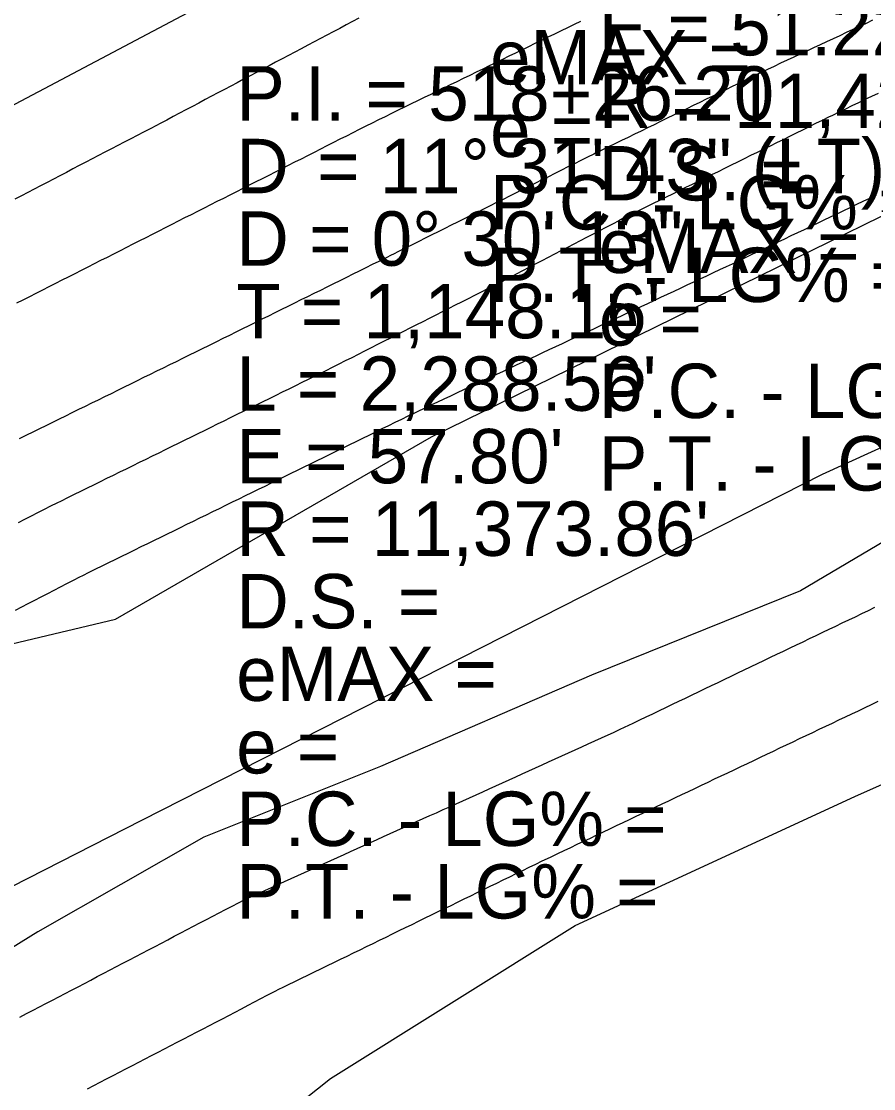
# Model space of a CAD drawing. Extents: x 1901471 to 1963503, y 756461 to 799997.
# Drawn here: x 1928579.4 to 1928696.9, y 772434.5 to 772581.7 of the extents above; entities that cross this region are included whole.
import ezdxf

# ---------------------------------------------------------------- set-up
doc = ezdxf.new("R2010")
doc.units = 0
for name, color, linetype in [('RD_EX_Fence_Other', 7, 'Continuous'), ('RD_EX_H2O', 7, 'Continuous'), ('RD_EX_Road', 7, 'Continuous'), ('RD_EX_VEG', 7, 'Continuous'), ('RD_HC_Cl', 7, 'Continuous'), ('RD_HC_Data', 7, 'Continuous')]:
    doc.layers.add(name, color=color, linetype=linetype)

msp = doc.modelspace()

# ---------------------------------------------------------------- linework, layer by layer
at = {"layer": 'RD_EX_Fence_Other'}
msp.add_lwpolyline([(1928895.27, 772596.98), (1928834.61, 772577.29), (1928778.94, 772557.41), (1928733.95, 772539.37), (1928689.79, 772519.2), (1928595.92, 772471.51), (1928519.66, 772432.64), (1928471.08, 772408.71), (1928397.76, 772375.45), (1928284.7, 772325.12), (1928290.51, 772300.92), (1928299.59, 772264.01), (1928266.54, 772247.26), (1928155.59, 772193.61), (1928053.03, 772134.41), (1927953.68, 772074.71)], dxfattribs=at)
at = {"layer": 'RD_EX_H2O'}
msp.add_lwpolyline([(1928578.56, 772500.51), (1928579.45, 772500.97), (1928580.33, 772501.43), (1928581.22, 772501.89), (1928582.11, 772502.35), (1928583, 772502.81), (1928583.88, 772503.27), (1928584.77, 772503.73), (1928585.66, 772504.19), (1928586.55, 772504.65), (1928587.43, 772505.11), (1928587.83, 772505.31), (1928588.73, 772505.75), (1928589.63, 772506.19), (1928590.52, 772506.63), (1928591.42, 772507.07), (1928592.32, 772507.51), (1928593.22, 772507.95), (1928594.11, 772508.39), (1928595.01, 772508.83), (1928595.91, 772509.27), (1928596.81, 772509.71), (1928597.71, 772510.15), (1928598.6, 772510.59), (1928599.5, 772511.03), (1928600.4, 772511.47), (1928601.3, 772511.91), (1928602.2, 772512.35), (1928603.09, 772512.79), (1928603.99, 772513.23), (1928604.89, 772513.67), (1928605.79, 772514.11), (1928606.69, 772514.55), (1928607.58, 772514.99), (1928608.48, 772515.43), (1928609.38, 772515.87), (1928610.28, 772516.31), (1928611.17, 772516.75), (1928612.07, 772517.19), (1928612.97, 772517.63), (1928613.87, 772518.07), (1928614.77, 772518.51), (1928615.66, 772518.95), (1928616.56, 772519.39), (1928617.46, 772519.83), (1928618.36, 772520.27), (1928619.26, 772520.71), (1928620.15, 772521.15), (1928621.05, 772521.58), (1928621.95, 772522.02), (1928622.85, 772522.46), (1928623.74, 772522.9), (1928624.64, 772523.34), (1928625.54, 772523.78), (1928626.44, 772524.22), (1928627.34, 772524.66), (1928628.23, 772525.1), (1928629.13, 772525.54), (1928630.03, 772525.98), (1928630.93, 772526.42), (1928631.83, 772526.86), (1928632.72, 772527.3), (1928633.62, 772527.74), (1928634.07, 772527.96), (1928634.97, 772528.38), (1928635.88, 772528.81), (1928636.78, 772529.23), (1928637.69, 772529.66), (1928638.59, 772530.08), (1928639.5, 772530.51), (1928640.4, 772530.93), (1928641.31, 772531.35), (1928642.21, 772531.78), (1928643.12, 772532.2), (1928644.02, 772532.63), (1928644.93, 772533.05), (1928644.93, 772533.05), (1928645.83, 772533.48), (1928646.74, 772533.9), (1928647.64, 772534.32), (1928648.55, 772534.75), (1928649.46, 772535.17), (1928650.36, 772535.6), (1928651.27, 772536.02), (1928652.17, 772536.44), (1928653.08, 772536.87), (1928653.98, 772537.29), (1928654.89, 772537.72), (1928655.79, 772538.14), (1928656.7, 772538.57), (1928657.6, 772538.99), (1928658.51, 772539.41), (1928659.41, 772539.84), (1928660.32, 772540.26), (1928661.22, 772540.69), (1928662.13, 772541.11), (1928663.03, 772541.54), (1928663.94, 772541.96), (1928664.84, 772542.38), (1928665.75, 772542.81), (1928666.65, 772543.23), (1928667.56, 772543.66), (1928668.46, 772544.08), (1928669.37, 772544.5), (1928670.27, 772544.93), (1928671.18, 772545.35), (1928672.08, 772545.78), (1928672.99, 772546.2), (1928673.89, 772546.63), (1928674.8, 772547.05), (1928675.7, 772547.47), (1928676.61, 772547.9), (1928677.43, 772548.28), (1928678.33, 772548.71), (1928679.23, 772549.14), (1928680.13, 772549.58), (1928681.04, 772550.01), (1928681.94, 772550.44), (1928682.84, 772550.87), (1928683.74, 772551.3), (1928684.64, 772551.73), (1928685.54, 772552.16), (1928686.45, 772552.59), (1928687.35, 772553.02), (1928688.25, 772553.45), (1928689.15, 772553.88), (1928690.05, 772554.31), (1928690.95, 772554.75), (1928691.86, 772555.18), (1928692.76, 772555.61), (1928693.66, 772556.04), (1928694.56, 772556.47), (1928695.46, 772556.9), (1928696.36, 772557.33), (1928697.27, 772557.76)], dxfattribs=at)
at = {"layer": 'RD_EX_Road'}
for points in [[(1928625.92, 772582.14), (1928625.03, 772581.67), (1928624.15, 772581.2), (1928623.27, 772580.73), (1928622.38, 772580.26), (1928621.5, 772579.8), (1928620.62, 772579.33), (1928619.73, 772578.86), (1928618.85, 772578.39), (1928617.97, 772577.92), (1928617.08, 772577.45), (1928616.2, 772576.99), (1928615.32, 772576.52), (1928614.43, 772576.05), (1928613.55, 772575.58), (1928612.67, 772575.11), (1928611.78, 772574.65), (1928610.9, 772574.18), (1928610.02, 772573.71), (1928609.13, 772573.24), (1928608.25, 772572.77), (1928607.37, 772572.3), (1928606.48, 772571.84), (1928605.6, 772571.37), (1928604.72, 772570.9), (1928603.83, 772570.43), (1928602.95, 772569.96), (1928602.07, 772569.5), (1928601.18, 772569.03), (1928600.3, 772568.56), (1928599.42, 772568.09), (1928598.53, 772567.62), (1928598, 772567.34), (1928597.11, 772566.88), (1928596.22, 772566.42), (1928595.34, 772565.95), (1928594.45, 772565.49), (1928593.56, 772565.03), (1928592.68, 772564.57), (1928591.79, 772564.11), (1928590.9, 772563.65), (1928590.02, 772563.18), (1928589.13, 772562.72), (1928588.24, 772562.26), (1928587.36, 772561.8), (1928586.47, 772561.34), (1928585.58, 772560.87), (1928584.69, 772560.41), (1928583.81, 772559.95), (1928582.92, 772559.49), (1928582.03, 772559.03), (1928581.15, 772558.57), (1928580.26, 772558.1), (1928579.37, 772557.64), (1928578.49, 772557.18)], [(1928578.75, 772542.87), (1928579.64, 772543.32), (1928580.53, 772543.78), (1928581.42, 772544.23), (1928582.31, 772544.68), (1928583.21, 772545.13), (1928584.1, 772545.58), (1928584.99, 772546.04), (1928585.88, 772546.49), (1928586.77, 772546.94), (1928587.66, 772547.39), (1928588.56, 772547.84), (1928589.45, 772548.3), (1928590.34, 772548.75), (1928591.23, 772549.2), (1928592.12, 772549.65), (1928593.02, 772550.1), (1928593.91, 772550.56), (1928594.8, 772551.01), (1928595.69, 772551.46), (1928596.58, 772551.91), (1928597.47, 772552.37), (1928598.37, 772552.82), (1928599.26, 772553.27), (1928600.15, 772553.72), (1928601.04, 772554.17), (1928601.93, 772554.63), (1928602.82, 772555.08), (1928603.72, 772555.53), (1928604.61, 772555.98), (1928605.5, 772556.43), (1928606.39, 772556.89), (1928607.28, 772557.34), (1928608.17, 772557.79), (1928609.07, 772558.24), (1928609.96, 772558.69), (1928610.85, 772559.15), (1928611.74, 772559.6), (1928612.63, 772560.05), (1928613.52, 772560.5), (1928614.42, 772560.95), (1928615.31, 772561.41), (1928616.2, 772561.86), (1928617.09, 772562.31), (1928617.98, 772562.76), (1928618.87, 772563.21), (1928619.77, 772563.67), (1928620.66, 772564.12), (1928621.55, 772564.57), (1928622.44, 772565.02), (1928623.33, 772565.48), (1928624.23, 772565.93), (1928625.12, 772566.38), (1928626.01, 772566.83), (1928626.9, 772567.28), (1928627.77, 772567.72), (1928628.67, 772568.16), (1928629.57, 772568.6), (1928630.46, 772569.04), (1928631.36, 772569.48), (1928632.26, 772569.91), (1928633.16, 772570.35), (1928634.06, 772570.79), (1928634.96, 772571.23), (1928635.86, 772571.66), (1928636.75, 772572.1), (1928637.65, 772572.54), (1928638.55, 772572.98), (1928639.45, 772573.42), (1928640.35, 772573.85), (1928641.25, 772574.29), (1928642.15, 772574.73), (1928643.05, 772575.17), (1928643.94, 772575.61), (1928644.84, 772576.04), (1928645.74, 772576.48), (1928646.64, 772576.92), (1928647.54, 772577.36), (1928648.44, 772577.79), (1928649.34, 772578.23), (1928650.23, 772578.67), (1928651.13, 772579.11), (1928652.03, 772579.55), (1928652.93, 772579.98), (1928653.83, 772580.42), (1928654.73, 772580.86), (1928655.63, 772581.3), (1928656.53, 772581.74)], [(1928696.74, 772581.84), (1928695.84, 772581.41), (1928694.93, 772580.99), (1928694.02, 772580.57), (1928693.12, 772580.14), (1928692.21, 772579.72), (1928691.31, 772579.3), (1928690.4, 772578.87), (1928689.5, 772578.45), (1928688.59, 772578.03), (1928687.69, 772577.6), (1928686.78, 772577.18), (1928685.88, 772576.76), (1928684.97, 772576.33), (1928684.07, 772575.91), (1928683.16, 772575.49), (1928682.26, 772575.06), (1928681.89, 772574.89), (1928680.99, 772574.45), (1928680.09, 772574.02), (1928679.2, 772573.58), (1928678.3, 772573.14), (1928677.4, 772572.7), (1928676.5, 772572.27), (1928675.6, 772571.83), (1928674.7, 772571.39), (1928673.8, 772570.95), (1928672.91, 772570.51), (1928672.01, 772570.08), (1928671.11, 772569.64), (1928670.21, 772569.2), (1928669.31, 772568.76), (1928668.41, 772568.33), (1928667.51, 772567.89), (1928666.61, 772567.45), (1928665.72, 772567.01), (1928664.82, 772566.57), (1928663.92, 772566.14), (1928663.02, 772565.7), (1928662.12, 772565.26), (1928661.22, 772564.82), (1928660.32, 772564.39), (1928659.43, 772563.95), (1928658.53, 772563.51), (1928658.31, 772563.4), (1928657.42, 772562.96), (1928656.52, 772562.51), (1928655.63, 772562.06), (1928654.73, 772561.62), (1928653.84, 772561.17), (1928652.94, 772560.72), (1928652.05, 772560.28), (1928651.16, 772559.83), (1928650.26, 772559.38), (1928649.37, 772558.94), (1928648.47, 772558.49), (1928647.58, 772558.04), (1928646.69, 772557.6), (1928645.79, 772557.15), (1928644.9, 772556.7), (1928644, 772556.26), (1928643.11, 772555.81), (1928642.21, 772555.36), (1928641.32, 772554.92), (1928640.43, 772554.47), (1928639.53, 772554.02), (1928638.64, 772553.58), (1928637.74, 772553.13), (1928636.85, 772552.68), (1928635.96, 772552.24), (1928635.06, 772551.79), (1928634.17, 772551.34), (1928633.27, 772550.9), (1928632.38, 772550.45), (1928631.48, 772550), (1928630.59, 772549.56), (1928630.45, 772549.49), (1928629.56, 772549.04), (1928628.66, 772548.6), (1928627.76, 772548.16), (1928626.87, 772547.71), (1928625.97, 772547.27), (1928625.08, 772546.83), (1928624.18, 772546.38), (1928623.29, 772545.94), (1928622.39, 772545.5), (1928621.5, 772545.05), (1928620.6, 772544.61), (1928619.71, 772544.17), (1928618.81, 772543.72), (1928617.92, 772543.28), (1928617.02, 772542.83), (1928616.12, 772542.39), (1928615.23, 772541.95), (1928614.33, 772541.5), (1928613.44, 772541.06), (1928612.54, 772540.62), (1928611.65, 772540.17), (1928610.75, 772539.73), (1928609.86, 772539.29), (1928608.96, 772538.84), (1928608.07, 772538.4), (1928607.17, 772537.96), (1928606.28, 772537.51), (1928606.09, 772537.42), (1928605.19, 772536.98), (1928604.3, 772536.54), (1928603.4, 772536.1), (1928602.5, 772535.66), (1928601.61, 772535.22), (1928600.71, 772534.77), (1928599.81, 772534.33), (1928598.91, 772533.89), (1928598.02, 772533.45), (1928597.12, 772533.01), (1928596.22, 772532.57), (1928595.32, 772532.13), (1928594.43, 772531.69), (1928593.53, 772531.24), (1928592.63, 772530.8), (1928591.74, 772530.36), (1928590.84, 772529.92), (1928589.94, 772529.48), (1928589.04, 772529.04), (1928588.15, 772528.6), (1928587.25, 772528.16), (1928586.35, 772527.71), (1928585.45, 772527.27), (1928584.56, 772526.83), (1928583.66, 772526.39), (1928582.76, 772525.95), (1928581.87, 772525.51), (1928580.97, 772525.07), (1928580.07, 772524.63), (1928579.97, 772524.58), (1928579.08, 772524.13)], [(1928697.5, 772571.77), (1928696.6, 772571.33), (1928695.7, 772570.9), (1928694.8, 772570.46), (1928693.9, 772570.03), (1928693, 772569.59), (1928692.1, 772569.16), (1928691.2, 772568.72), (1928690.69, 772568.47), (1928689.79, 772568.03), (1928688.89, 772567.59), (1928688, 772567.15), (1928687.1, 772566.71), (1928686.2, 772566.27), (1928685.31, 772565.83), (1928684.41, 772565.38), (1928683.51, 772564.94), (1928682.61, 772564.5), (1928681.72, 772564.06), (1928680.82, 772563.62), (1928679.92, 772563.18), (1928679.03, 772562.74), (1928678.13, 772562.3), (1928677.23, 772561.85), (1928676.34, 772561.41), (1928675.44, 772560.97), (1928674.54, 772560.53), (1928673.64, 772560.09), (1928672.75, 772559.65), (1928671.85, 772559.21), (1928670.95, 772558.77), (1928670.06, 772558.33), (1928669.16, 772557.88), (1928668.26, 772557.44), (1928667.37, 772557), (1928666.47, 772556.56), (1928665.57, 772556.12), (1928664.67, 772555.68), (1928663.78, 772555.24), (1928662.88, 772554.8), (1928662.63, 772554.68), (1928661.75, 772554.21), (1928660.86, 772553.75), (1928659.98, 772553.29), (1928659.09, 772552.83), (1928658.21, 772552.36), (1928657.32, 772551.9), (1928656.44, 772551.44), (1928655.55, 772550.98), (1928654.67, 772550.52), (1928653.78, 772550.05), (1928652.9, 772549.59), (1928652.01, 772549.13), (1928651.13, 772548.67), (1928650.24, 772548.2), (1928649.35, 772547.74), (1928648.47, 772547.28), (1928647.58, 772546.82), (1928646.7, 772546.35), (1928646.33, 772546.16), (1928645.43, 772545.71), (1928644.54, 772545.26), (1928643.65, 772544.81), (1928642.76, 772544.35), (1928641.87, 772543.9), (1928640.97, 772543.45), (1928640.08, 772543), (1928639.19, 772542.55), (1928638.3, 772542.1), (1928637.41, 772541.64), (1928636.52, 772541.19), (1928635.62, 772540.74), (1928634.73, 772540.29), (1928633.84, 772539.84), (1928632.95, 772539.39), (1928632.06, 772538.93), (1928631.16, 772538.48), (1928630.27, 772538.03), (1928629.38, 772537.58), (1928628.49, 772537.13), (1928627.6, 772536.68), (1928626.7, 772536.22), (1928625.81, 772535.77), (1928624.92, 772535.32), (1928624.03, 772534.87), (1928623.14, 772534.42), (1928622.24, 772533.97), (1928621.35, 772533.51), (1928620.73, 772533.2), (1928619.84, 772532.76), (1928618.94, 772532.32), (1928618.04, 772531.88), (1928617.15, 772531.44), (1928616.25, 772531), (1928615.35, 772530.56), (1928614.45, 772530.11), (1928613.56, 772529.67), (1928612.66, 772529.23), (1928611.76, 772528.79), (1928610.87, 772528.35), (1928609.97, 772527.91), (1928609.07, 772527.47), (1928608.17, 772527.03), (1928607.28, 772526.59), (1928606.38, 772526.15), (1928605.48, 772525.7), (1928604.59, 772525.26), (1928603.69, 772524.82), (1928602.79, 772524.38), (1928601.89, 772523.94), (1928601, 772523.5), (1928600.1, 772523.06), (1928599.2, 772522.62), (1928598.31, 772522.18), (1928597.41, 772521.74), (1928596.51, 772521.29), (1928595.61, 772520.85), (1928594.72, 772520.41), (1928593.82, 772519.97), (1928592.92, 772519.53), (1928592.03, 772519.09), (1928591.13, 772518.65), (1928590.23, 772518.21), (1928589.33, 772517.77), (1928588.44, 772517.33), (1928587.54, 772516.89), (1928586.64, 772516.44), (1928585.75, 772516), (1928584.85, 772515.56), (1928584.28, 772515.28), (1928583.39, 772514.83), (1928582.5, 772514.38), (1928581.61, 772513.93), (1928580.71, 772513.48), (1928579.82, 772513.03), (1928578.93, 772512.57)], [(1928579.15, 772444.4), (1928580.1, 772444.89), (1928580.99, 772445.36), (1928581.87, 772445.82), (1928582.76, 772446.28), (1928583.64, 772446.75), (1928584.53, 772447.21), (1928585.41, 772447.67), (1928586.3, 772448.14), (1928587.18, 772448.6), (1928588.07, 772449.06), (1928588.95, 772449.52), (1928589.84, 772449.99), (1928590.72, 772450.45), (1928591.61, 772450.91), (1928592.49, 772451.38), (1928593.38, 772451.84), (1928594.27, 772452.3), (1928595.15, 772452.77), (1928596.04, 772453.23), (1928596.92, 772453.69), (1928597.81, 772454.16), (1928598.69, 772454.62), (1928599.58, 772455.08), (1928600.46, 772455.55), (1928601.35, 772456.01), (1928602.23, 772456.47), (1928603.12, 772456.94), (1928604, 772457.4), (1928604.89, 772457.86), (1928605.77, 772458.33), (1928606.66, 772458.79), (1928607.54, 772459.25), (1928608.43, 772459.72), (1928609.31, 772460.18), (1928610.2, 772460.64), (1928611.11, 772461.05), (1928612.02, 772461.47), (1928612.93, 772461.88), (1928613.84, 772462.29), (1928614.75, 772462.7), (1928615.66, 772463.11), (1928616.57, 772463.53), (1928617.48, 772463.94), (1928618.39, 772464.35), (1928619.31, 772464.76), (1928620.22, 772465.18), (1928621.13, 772465.59), (1928622.04, 772466), (1928622.95, 772466.41), (1928623.86, 772466.82), (1928624.77, 772467.24), (1928625.68, 772467.65), (1928626.59, 772468.06), (1928627.5, 772468.47), (1928628.41, 772468.88), (1928629.32, 772469.3), (1928630.23, 772469.71), (1928631.14, 772470.12), (1928632.96, 772470.95), (1928633.87, 772471.36), (1928634.78, 772471.77), (1928635.69, 772472.18), (1928636.6, 772472.59), (1928637.52, 772473.01), (1928638.43, 772473.42), (1928639.34, 772473.83), (1928640.25, 772474.24), (1928641.16, 772474.65), (1928642.07, 772475.07), (1928642.98, 772475.48), (1928643.89, 772475.89), (1928645.71, 772476.72), (1928646.62, 772477.13), (1928647.53, 772477.54), (1928648.44, 772477.95), (1928649.35, 772478.36), (1928650.26, 772478.78), (1928651.17, 772479.19), (1928652.08, 772479.6), (1928652.99, 772480.01), (1928653.9, 772480.43), (1928654.81, 772480.84), (1928655.73, 772481.25), (1928656.64, 772481.66), (1928657.55, 772482.07), (1928658.46, 772482.49), (1928659.37, 772482.9), (1928660.28, 772483.31), (1928661.04, 772483.66), (1928661.94, 772484.09), (1928663.74, 772484.95), (1928664.64, 772485.38), (1928665.54, 772485.81), (1928666.45, 772486.24), (1928667.35, 772486.67), (1928668.25, 772487.11), (1928669.15, 772487.54), (1928670.05, 772487.97), (1928670.95, 772488.4), (1928670.95, 772488.4), (1928671.85, 772488.83), (1928672.75, 772489.26), (1928673.65, 772489.69), (1928674.55, 772490.12), (1928675.45, 772490.56), (1928676.35, 772490.99), (1928677.26, 772491.42), (1928678.16, 772491.85), (1928679.06, 772492.28), (1928680.86, 772493.14), (1928681.76, 772493.57), (1928682.66, 772494.01), (1928683.56, 772494.44), (1928684.46, 772494.87), (1928685.36, 772495.3), (1928686.26, 772495.73), (1928687.16, 772496.16), (1928688.06, 772496.59), (1928688.97, 772497.03), (1928689.87, 772497.46), (1928690.77, 772497.89), (1928691.67, 772498.32), (1928692.57, 772498.75), (1928693.47, 772499.18), (1928694.37, 772499.61), (1928695.27, 772500.04), (1928696.17, 772500.48), (1928697.07, 772500.91)], [(1928697.46, 772487.9), (1928696.56, 772487.47), (1928695.66, 772487.04), (1928694.75, 772486.61), (1928693.85, 772486.18), (1928692.95, 772485.76), (1928692.05, 772485.33), (1928691.15, 772484.9), (1928690.25, 772484.47), (1928689.34, 772484.04), (1928688.44, 772483.61), (1928687.54, 772483.19), (1928686.64, 772482.76), (1928685.74, 772482.33), (1928684.84, 772481.9), (1928683.93, 772481.47), (1928683.03, 772481.04), (1928682.13, 772480.61), (1928681.23, 772480.19), (1928680.33, 772479.76), (1928679.43, 772479.33), (1928678.52, 772478.9), (1928677.62, 772478.47), (1928676.72, 772478.04), (1928675.82, 772477.62), (1928674.92, 772477.19), (1928674.02, 772476.76), (1928673.11, 772476.33), (1928672.21, 772475.9), (1928671.31, 772475.47), (1928670.41, 772475.05), (1928669.51, 772474.62), (1928668.61, 772474.19), (1928667.7, 772473.76), (1928666.8, 772473.33), (1928665.9, 772472.9), (1928665, 772472.47), (1928664.1, 772472.05), (1928663.2, 772471.62), (1928662.29, 772471.19), (1928661.39, 772470.76), (1928660.49, 772470.33), (1928659.59, 772469.9), (1928658.69, 772469.48), (1928657.79, 772469.05), (1928656.88, 772468.62), (1928655.98, 772468.19), (1928655.08, 772467.76), (1928654.18, 772467.33), (1928653.28, 772466.91), (1928652.38, 772466.48), (1928651.47, 772466.05), (1928651.15, 772465.89), (1928650.25, 772465.46), (1928650.25, 772465.46), (1928649.35, 772465.02), (1928648.46, 772464.58), (1928647.56, 772464.15), (1928646.66, 772463.71), (1928645.77, 772463.27), (1928644.87, 772462.83), (1928643.97, 772462.4), (1928643.07, 772461.96), (1928642.18, 772461.52), (1928641.28, 772461.09), (1928640.38, 772460.65), (1928639.48, 772460.21), (1928638.59, 772459.77), (1928637.69, 772459.34), (1928636.79, 772458.9), (1928635.89, 772458.46), (1928635, 772458.03), (1928634.1, 772457.59), (1928633.2, 772457.15), (1928632.3, 772456.71), (1928631.41, 772456.28), (1928630.51, 772455.84), (1928629.61, 772455.4), (1928628.71, 772454.97), (1928627.82, 772454.53), (1928626.92, 772454.09), (1928626.02, 772453.65), (1928625.12, 772453.22), (1928624.23, 772452.78), (1928623.33, 772452.34), (1928622.43, 772451.91), (1928621.53, 772451.47), (1928620.64, 772451.03), (1928619.74, 772450.59), (1928618.84, 772450.16), (1928617.94, 772449.72), (1928617.05, 772449.28), (1928616.15, 772448.85), (1928615.25, 772448.41), (1928615.02, 772448.29), (1928614.13, 772447.83), (1928613.24, 772447.37), (1928612.36, 772446.91), (1928611.47, 772446.45), (1928610.58, 772445.99), (1928609.7, 772445.52), (1928608.81, 772445.06), (1928607.92, 772444.6), (1928607.04, 772444.14), (1928606.15, 772443.68), (1928605.26, 772443.22), (1928604.38, 772442.76), (1928603.49, 772442.29), (1928602.6, 772441.83), (1928601.72, 772441.37), (1928600.83, 772440.91), (1928599.94, 772440.45), (1928599.06, 772439.99), (1928598.17, 772439.52), (1928597.28, 772439.06), (1928596.4, 772438.6), (1928595.51, 772438.14), (1928594.63, 772437.68), (1928593.74, 772437.22), (1928592.85, 772436.75), (1928591.97, 772436.29), (1928591.08, 772435.83), (1928590.19, 772435.37), (1928589.31, 772434.91), (1928588.42, 772434.45)]]:
    msp.add_lwpolyline(points, dxfattribs=at)
at = {"layer": 'RD_EX_VEG'}
for points in [[(1928566.62, 772493.18), (1928592.33, 772499.26), (1928635.93, 772524.43), (1928719.36, 772565.3), (1928772.65, 772586.37), (1928795.36, 772604.13), (1928811, 772606.06), (1928836.41, 772606.03), (1928863.91, 772614.6), (1928890.82, 772620.55), (1928901.78, 772617.79), (1928939.07, 772631.97)], [(1928606.54, 772423.69), (1928621.98, 772435.95), (1928655.75, 772457.04), (1928694.32, 772474.84), (1928743.67, 772496.78), (1928818.93, 772525.36), (1928866.78, 772542.99), (1928894.51, 772551.34), (1928897.57, 772558.03), (1928897.31, 772568.97), (1928892.65, 772579.1), (1928879.96, 772580.34), (1928842.08, 772570.79), (1928797.08, 772556.6), (1928768.67, 772542.11), (1928745.52, 772534.93), (1928709.17, 772516.41), (1928686.82, 772503.17), (1928657.99, 772491.55), (1928628.91, 772478.94), (1928604.55, 772469.22), (1928581.64, 772456.17), (1928567.32, 772447.31)]]:
    msp.add_lwpolyline(points, dxfattribs=at)
at = {"layer": 'RD_HC_Cl'}
for centre, radius, start, end in [((1933934.02, 762479.74), 11482.38, 112.01316, 122.84589), ((1933920.67, 762509.14), 11420.5, 112.014247, 122.846378), ((1933910.03, 762523.4), 11373.86, 112.013249, 123.541888)]:
    msp.add_arc(centre, radius, start, end, dxfattribs=at)

# ---------------------------------------------------------------- texts
at = {"layer": 'RD_HC_Data'}
for s, p in [("E = 51.22'", (1928659, 772577)), ('eMAX = ', (1928644, 772573)), ('P.I. = 518+26.20', (1928609, 772568)), ("R = 11,420.50'", (1928659, 772567)), ('e = ', (1928644, 772563)), ('D', (1928609, 772558)), ('    = 11%%d 31\' 43" (LT)', (1928609, 772558)), ('D.S. = ', (1928659, 772557)), ('P.C. - LG% = ', (1928644, 772553)), ('D = 0%%d 30\' 13"', (1928609, 772548)), ('eMAX = ', (1928659, 772547)), ('P.T. - LG% = ', (1928644, 772543)), ("T = 1,148.16'", (1928609, 772538)), ('e = ', (1928659, 772537)), ("L = 2,288.56'", (1928609, 772528)), ('P.C. - LG% = ', (1928659, 772527)), ("E = 57.80'", (1928609, 772518)), ('P.T. - LG% = ', (1928659, 772517)), ("R = 11,373.86'", (1928609, 772508)), ('D.S. = ', (1928609, 772498)), ('eMAX = ', (1928609, 772488)), ('e = ', (1928609, 772478)), ('P.C. - LG% = ', (1928609, 772468)), ('P.T. - LG% = ', (1928609, 772458))]:
    msp.add_text(s, height=7.5, dxfattribs=at).set_placement(p)

doc.saveas('drawing.dxf')
